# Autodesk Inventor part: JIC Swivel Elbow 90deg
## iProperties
Category: Hydraulics
Title: JIC Swivel Elbow 90deg
Subject: Hydraulic Adapters
Author: QBZ
Shininess: 27.0
PropertySet Name: _Private Model Information
Created: 2001-03
Part Number: 2071-8-8S
Document SubType Name: Modeling
Designer: QBZ
Description: JIC Swivel Elbow 90  8-8
Material: Steel, Mild
Catalog Web Link: http://www.aeroquip.com
Control State: 0
Master: False
Checked Out: False
PropertySet Name: Design Tracking Control
Density: 7.859999999999999
Volumn: 12.768401423356869
Area: 73.09805400316779
PropertySet Name: Model Information
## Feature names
1. Male Body [Extrusion]
2. Female Body [Extrusion]
3. Revolution1
4. Male JIC [Revolution]
5. Female JIC [Revolution]
6. Hex [Extrusion]
7. Revolution4
8. Female ID
9. Male ID [Hole]
10. Fillet1
